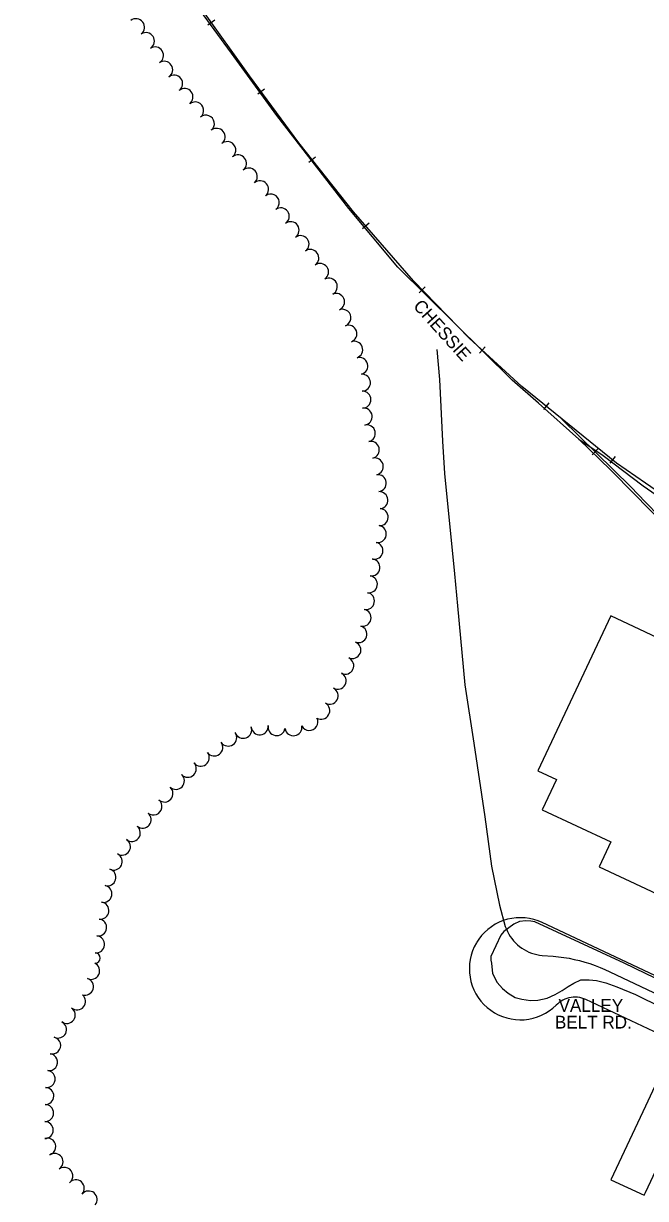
# Model space of a CAD drawing. Extents: x -25029 to 2274964, y -81170 to 687028.
# Drawn here: x -10478 to -9748, y -65025 to -63645 of the extents above; entities that cross this region are included whole.
import ezdxf

# ---------------------------------------------------------------- set-up
doc = ezdxf.new("R2010")
doc.units = 0
for name, color, linetype in [('81911BEA - RW_X_Fee_RW', 7, 'Continuous'), ('BLDG', 7, 'Continuous'), ('GE_X_CL_2000', 7, 'Continuous'), ('RD_X_RR_1', 7, 'Continuous'), ('ROAD', 7, 'Continuous'), ('ROAD-NAME', 7, 'Continuous'), ('RR', 7, 'Continuous'), ('TREES', 7, 'Continuous')]:
    doc.layers.add(name, color=color, linetype=linetype)

msp = doc.modelspace()

# ---------------------------------------------------------------- linework, layer by layer
at = {"layer": '81911BEA - RW_X_Fee_RW'}
msp.add_line((-9519.5, -64865.7), (-9869.5, -64700.6), dxfattribs=at)
for points in [[(-9869.5, -64700.6), (-9874.4, -64698.6), (-9879.3, -64697), (-9884.4, -64695.8), (-9889.6, -64695.1), (-9894.8, -64694.9), (-9900.1, -64695.1), (-9905.2, -64695.7), (-9910.3, -64696.8), (-9915.3, -64698.4), (-9920.2, -64700.3), (-9924.8, -64702.7), (-9929.2, -64705.5), (-9933.4, -64708.7), (-9937.3, -64712.2), (-9940.8, -64716), (-9944.1, -64720.1), (-9946.4, -64723.8), (-9946.9, -64724.5), (-9949.3, -64729.1), (-9951.4, -64733.9), (-9953, -64738.9), (-9954.1, -64744), (-9954.9, -64749.2), (-9955.1, -64754.4), (-9955, -64759.6), (-9954.3, -64764.8), (-9953.2, -64769.9), (-9951.7, -64774.9), (-9949.7, -64779.7), (-9947.4, -64784.4), (-9944.6, -64788.8), (-9941.5, -64793), (-9938, -64796.9), (-9934.2, -64800.5), (-9930, -64803.7), (-9925.7, -64806.5), (-9921.1, -64809), (-9916.2, -64811), (-9911.3, -64812.7), (-9906.2, -64813.8), (-9901, -64814.6), (-9895.8, -64814.9), (-9890.6, -64814.7), (-9885.4, -64814.1), (-9880.3, -64813), (-9875.3, -64811.5), (-9870.4, -64809.5), (-9865.8, -64807.2), (-9861.3, -64804.4), (-9857.1, -64801.3), (-9853.2, -64797.8)], [(-9818.4, -64791.1), (-9820.7, -64790.1), (-9823.1, -64789.3), (-9825.6, -64788.7), (-9828.1, -64788.3), (-9830.6, -64788.2), (-9833.2, -64788.3), (-9835.7, -64788.5), (-9838.2, -64789), (-9840.6, -64789.7), (-9843, -64790.6), (-9845.2, -64791.7), (-9847.4, -64793), (-9849.5, -64794.4), (-9851.4, -64796), (-9853.2, -64797.8)], [(-9545.1, -64920), (-9665.5, -64863.2), (-9818.4, -64791.1)]]:
    msp.add_lwpolyline(points, dxfattribs=at)
at = {"layer": 'BLDG'}
for points in [[(-9748.4, -64359.6), (-9789.2, -64340.4), (-9874.8, -64522.3)], [(-9480.8, -64748.4), (-9379.5, -64533.2), (-9748.4, -64359.6)], [(-9874.8, -64522.3), (-9853, -64532.6), (-9869.7, -64568.1), (-9789.2, -64606), (-9802.9, -64635), (-9748.4, -64660.7)], [(-9748.4, -64660.7), (-9726.7, -64670.9), (-9713.6, -64643.1), (-9662.7, -64667), (-9675.7, -64694.6), (-9600.1, -64730.2), (-9586.9, -64702), (-9488.4, -64748.4)], [(-9716.2, -64858.8), (-9730.2, -64888.8), (-9734.5, -64886.8), (-9748.4, -64916.3)], [(-9748.4, -65017.8), (-9681.5, -64875.1), (-9716.2, -64858.8)], [(-9748.4, -64916.3), (-9788.9, -65002.8), (-9749.9, -65021), (-9748.4, -65017.8)]]:
    msp.add_lwpolyline(points, dxfattribs=at)
at = {"layer": 'GE_X_CL_2000'}
msp.add_lwpolyline([(-9993.1, -64027.4), (-9990, -64062.9), (-9986.8, -64135.1), (-9984.2, -64173.4), (-9972.6, -64291.1), (-9969.1, -64328.6), (-9960.4, -64421.5), (-9950, -64490), (-9937, -64576.3), (-9929.2, -64634.4), (-9919.8, -64680.4), (-9912.9, -64705.4), (-9911.7, -64708.4), (-9910.4, -64711.3), (-9908.9, -64714.2), (-9907.1, -64716.9), (-9905.3, -64719.5), (-9903.2, -64722), (-9901, -64724.4), (-9898.7, -64726.6), (-9896.2, -64728.7), (-9893.6, -64730.6), (-9890.9, -64732.3), (-9888.1, -64733.9), (-9885.2, -64735.3), (-9882.2, -64736.5), (-9879.1, -64737.5), (-9876, -64738.3), (-9872.8, -64739), (-9869.6, -64739.4), (-9856.9, -64740), (-9850.6, -64740.7), (-9844.3, -64741.5), (-9838.1, -64742.6), (-9831.9, -64743.9), (-9825.7, -64745.3), (-9819.6, -64747), (-9813.6, -64748.9), (-9807.6, -64751), (-9801.7, -64753.3), (-9795.9, -64755.8), (-9790.2, -64758.6), (-9702.5, -64800.2)], dxfattribs=at)
at = {"layer": 'RD_X_RR_1'}
for points in [[(-9826.6, -64133), (-9874.1, -64090.5), (-9904.9, -64063.6), (-10038.9, -63930.9), (-10096.7, -63861.9), (-10181.3, -63752.7), (-10234.3, -63679.5), (-10286.8, -63607.5)], [(-9826.6, -64133), (-9789.3, -64168.9), (-9761.1, -64197.4), (-9728.4, -64231.3), (-9699.8, -64264.2), (-9673.5, -64293.9), (-9642.2, -64329.8)], [(-9826.6, -64133), (-9798.2, -64152.1), (-9751, -64187.6), (-9702.8, -64221), (-9654.2, -64252.6), (-9611.2, -64278), (-9556, -64309.4), (-9504.4, -64336.8), (-9477.8, -64350), (-9444.5, -64366.3)]]:
    msp.add_lwpolyline(points, dxfattribs=at)
at = {"layer": 'ROAD'}
msp.add_line((-9748.4, -64760.4), (-9773.4, -64748.4), dxfattribs=at)
for points in [[(-9773.4, -64748.4), (-9878.2, -64699.8), (-9883.1, -64699), (-9889, -64698.7), (-9896.4, -64699.5), (-9902.8, -64702.5), (-9914.7, -64711), (-9918.2, -64715.5), (-9929.9, -64740.6), (-9929.8, -64744.9), (-9929.2, -64748.4)], [(-9929.2, -64748.4), (-9928.1, -64760.3), (-9922.5, -64771), (-9916.3, -64778), (-9909.6, -64783.7), (-9901.4, -64788.5), (-9893.7, -64790.7), (-9883.2, -64792.1), (-9874.7, -64791.8), (-9863.8, -64789.4), (-9854.2, -64785.1), (-9846.2, -64780.3), (-9839.2, -64775.8), (-9832.6, -64771.9), (-9824.2, -64768), (-9814.6, -64767.9), (-9805.9, -64768.8), (-9794.8, -64771.3), (-9781.9, -64776), (-9760.1, -64785.3), (-9748.4, -64790.9)], [(-9728.1, -64770.2), (-9748.4, -64760.4)], [(-9748.4, -64790.9), (-9671.3, -64827.6)]]:
    msp.add_lwpolyline(points, dxfattribs=at)
at = {"layer": 'RR'}
for p, q in [((-10253.9, -63640.7), (-10262, -63646.5)), ((-10195.5, -63721.8), (-10203.5, -63727.7)), ((-10135.7, -63801.7), (-10143.5, -63807.9)), ((-10072.9, -63879.3), (-10080.5, -63885.8)), ((-10006.9, -63954), (-10014.1, -63960.9)), ((-9936.6, -64024.6), (-9943.4, -64032)), ((-9861.7, -64090.4), (-9868, -64098.1)), ((-9804, -64144), (-9811, -64151.2)), ((-9784, -64153.4), (-9790.3, -64161.1))]:
    msp.add_line(p, q, dxfattribs=at)
for points in [[(-9748.4, -64184.6), (-9782.3, -64161.2), (-9893.4, -64071.1), (-9955.5, -64014.1), (-10020.8, -63946.9), (-10091.1, -63865.9), (-10155.3, -63784.9), (-10213.3, -63706), (-10269.2, -63628), (-10325.4, -63549.2), (-10391.3, -63455.8), (-10460.5, -63357.9), (-10478.5, -63332.4)], [(-9748.4, -64206.7), (-9765.5, -64189), (-9846.4, -64109.3)], [(-8123, -64584.1), (-8351.4, -64569.3), (-8550.3, -64554.7), (-8738.4, -64541.7), (-8817.7, -64534.7), (-8870.3, -64529.1), (-8945.3, -64518.6), (-9004, -64508.1), (-9104.9, -64485.3), (-9189, -64461.6), (-9278.4, -64432.1), (-9377.8, -64393.2), (-9451.7, -64359.8), (-9555.4, -64306.9), (-9661.5, -64244.3), (-9748.4, -64184.6)], [(-9209.1, -64579.1), (-9319.5, -64533.3), (-9426.3, -64481.9), (-9520.2, -64432.7), (-9557.1, -64407.6), (-9586.7, -64383), (-9627.7, -64341.1), (-9677.6, -64285.5), (-9732.2, -64223.5), (-9748.4, -64206.7)]]:
    msp.add_lwpolyline(points, dxfattribs=at)
at = {"layer": 'TREES'}
for centre, radius, start, end in [((-10346.4, -63649), 10, 307.327, 127.327), ((-10334.8, -63665.3), 10, 302.9459, 122.9459), ((-10324.1, -63682.2), 10, 302.1488, 122.1488), ((-10313.3, -63699), 10, 303.4277, 123.4277), ((-10301.7, -63715.3), 10, 307.375, 127.375), ((-10289.5, -63731.1), 10, 307.7234, 127.7234), ((-10277, -63746.8), 10, 309.2675, 129.2675), ((-10264.4, -63762.3), 10, 309.2675, 129.2675), ((-10251.8, -63777.8), 10, 308.9853, 128.9853), ((-10239.3, -63793.4), 10, 308.4376, 128.4376), ((-10226.8, -63809), 10, 308.643, 128.643), ((-10214, -63824.4), 10, 311.1897, 131.1897), ((-10200.8, -63839.4), 10, 311.1897, 131.1897), ((-10188.2, -63855), 10, 306.6142, 126.6142), ((-10176.5, -63871.2), 10, 305.0751, 125.0751), ((-10165, -63887.5), 10, 305.5848, 125.5848), ((-10153.3, -63903.8), 10, 305.5848, 125.5848), ((-10141.8, -63920.1), 10, 304.842, 124.842), ((-10130.4, -63936.5), 10, 304.6938, 124.6938), ((-10120.1, -63953.7), 10, 297.1605, 117.1605), ((-10111.6, -63971.7), 10, 293.6728, 113.6728), ((-10104.1, -63990.3), 10, 290.3722, 110.3722), ((-10097.1, -64009), 10, 290.1954, 110.1954), ((-10090.3, -64027.8), 10, 289.5761, 109.5761), ((-10084.3, -64046.9), 10, 285.5579, 105.5579), ((-10081.2, -64066.5), 10, 272.1233, 92.1233), ((-10080.7, -64086.5), 10, 270.7576, 90.7576), ((-10079.2, -64106.4), 10, 277.9991, 97.9991), ((-10075.5, -64126), 10, 283.3077, 103.3077), ((-10070.8, -64145.5), 10, 283.8767, 103.8767), ((-10066.1, -64164.9), 10, 283.5751, 103.5751), ((-10062.6, -64184.6), 10, 276.681, 96.681), ((-10060.7, -64204.5), 10, 274.1616, 94.1616), ((-10060.4, -64224.4), 10, 267.6216, 87.6216), ((-10062.6, -64244.3), 10, 259.6343, 79.6343), ((-10066.5, -64263.9), 10, 257.6091, 77.6091), ((-10070.1, -64283.5), 10, 261.9578, 81.9578), ((-10073.1, -64303.3), 10, 260.8544, 80.8544), ((-10076.5, -64323), 10, 259.1191, 79.1191), ((-10080.4, -64342.6), 10, 258.5577, 78.5577), ((-10085.5, -64361.9), 10, 251.804, 71.804), ((-10092.5, -64380.6), 10, 247.0382, 67.0382), ((-10100.8, -64398.9), 10, 244.4328, 64.4328), ((-10109.8, -64416.7), 10, 241.9308, 61.9308), ((-10119.2, -64434.3), 10, 241.5744, 61.5744), ((-10129, -64451.8), 10, 240.032, 60.032), ((-10142.9, -64465), 10, 207.2506, 27.2506), ((-10220.6, -64474.2), 10, 199.4407, 19.4407), ((-10201.2, -64470.1), 10, 184.8008, 4.8008), ((-10181.4, -64471), 10, 169.9318, 349.9318), ((-10161.6, -64471.2), 10, 189.0609, 9.0609), ((-10254.5, -64494.9), 10, 216.4776, 36.4776), ((-10238.2, -64483.3), 10, 214.7245, 34.7245), ((-10270.4, -64507), 10, 217.7594, 37.7594), ((-10285.6, -64520), 10, 223.6631, 43.6631), ((-10299.6, -64534.2), 10, 226.8694, 46.8694), ((-10313, -64549.1), 10, 228.9379, 48.9379), ((-10326, -64564.3), 10, 230.569, 50.569), ((-10338.6, -64579.8), 10, 230.8433, 50.8433), ((-10351.3, -64595.3), 10, 230.8889, 50.8889), ((-10362.9, -64611.5), 10, 237.8555, 57.8555), ((-10372.6, -64629), 10, 243.7921, 63.7921), ((-10379.9, -64647.5), 10, 253.5292, 73.5292), ((-10384.7, -64666.9), 10, 258.273, 78.273), ((-10388.2, -64686.6), 10, 261.8727, 81.8727), ((-10390.9, -64706.4), 10, 262.2782, 82.2782), ((-10393.3, -64726.3), 10, 264.0807, 84.0807), ((-10394.6, -64742.3), 6.08, 272.1221, 87.8778), ((-10399.1, -64757.4), 10, 244.2528, 64.2528), ((-10406.4, -64775.9), 10, 253.0821, 73.0821), ((-10415.6, -64793.3), 10, 230.6914, 50.6914), ((-10427.7, -64809.2), 10, 235.1219, 55.1219), ((-10437.9, -64826.3), 10, 243.4521, 63.4521), ((-10444.8, -64845), 10, 256.0428, 76.0428), ((-10448.5, -64864.6), 10, 262.1432, 82.1432), ((-10451.3, -64884.4), 10, 262.1432, 82.1432), ((-10452.9, -64904.3), 10, 268.5764, 88.5764), ((-10453.2, -64924.3), 10, 269.3771, 89.3771), ((-10453.5, -64944.3), 10, 269.3771, 89.3771), ((-10450.5, -64963.8), 10, 287.6764, 107.6764), ((-10442, -64981.7), 10, 303.3568, 123.3568), ((-10430.5, -64998.1), 10, 306.5352, 126.5352), ((-10417.1, -65012.8), 10, 318.302, 138.302), ((-10402, -65025.9), 10, 320.1789, 140.1789)]:
    msp.add_arc(centre, radius, start, end, dxfattribs=at)

# ---------------------------------------------------------------- texts
at = {"layer": 'ROAD-NAME'}
msp.add_text('CHESSIE', height=15, rotation=312.0064, dxfattribs=at).set_placement((-10021.9, -63977.2))
for s, p in [('VALLEY', (-9850.4, -64805.5)), ('BELT RD.', (-9854.7, -64825.1))]:
    msp.add_text(s, height=15, dxfattribs=at).set_placement(p)

doc.saveas('drawing.dxf')
